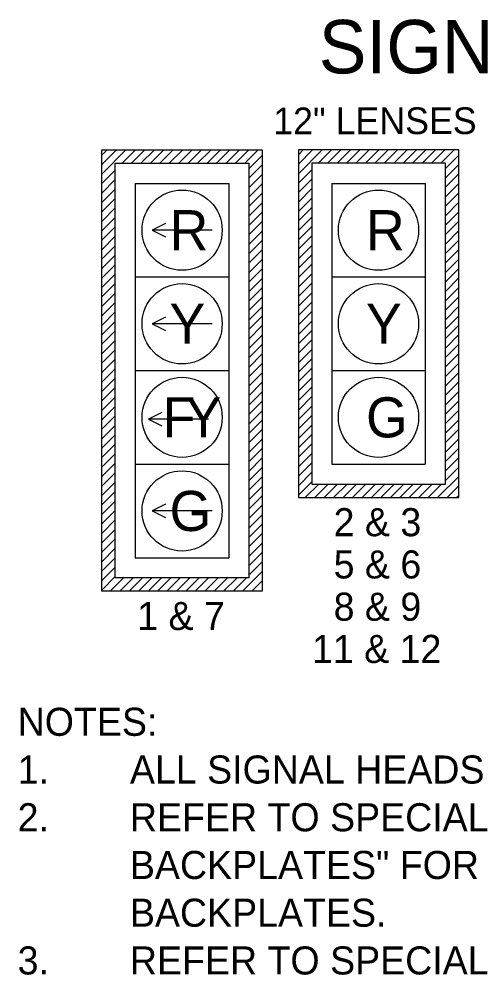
# Model space of a CAD drawing. Extents: x 418532 to 419834, y -565899 to -565283.
# Drawn here: x 419059.3 to 419129, y -565425.8 to -565282.9 of the extents above; entities that cross this region are included whole.
import ezdxf

# ---------------------------------------------------------------- set-up
doc = ezdxf.new("R2010")
doc.units = 0
for name, color, linetype in [('C-ANNO-TEXT', 7, 'Continuous'), ('Level 61', 7, 'Continuous'), ('T_Drafting', 7, 'Continuous')]:
    doc.layers.add(name, color=color, linetype=linetype)

msp = doc.modelspace()

# ---------------------------------------------------------------- linework, layer by layer
at = {"layer": 'T_Drafting'}
for p, q in [((419071.67, -565368.43), (419071.67, -565302.43)), ((419071.67, -565302.43), (419095.67, -565302.43)), ((419071.67, -565306.04), (419075.27, -565302.43)), ((419071.67, -565304.62), (419073.86, -565302.43)), ((419071.67, -565303.21), (419072.45, -565302.43)), ((419074.69, -565304.43), (419076.69, -565302.43)), ((419076.1, -565304.43), (419078.1, -565302.43)), ((419077.52, -565304.43), (419079.52, -565302.43)), ((419078.93, -565304.43), (419080.93, -565302.43)), ((419080.35, -565304.43), (419082.35, -565302.43)), ((419081.76, -565304.43), (419083.76, -565302.43)), ((419083.17, -565304.43), (419085.17, -565302.43)), ((419084.59, -565304.43), (419086.59, -565302.43)), ((419086, -565304.43), (419088, -565302.43)), ((419087.42, -565304.43), (419089.42, -565302.43)), ((419088.83, -565304.43), (419090.83, -565302.43)), ((419090.25, -565304.43), (419092.25, -565302.43)), ((419091.66, -565304.43), (419093.66, -565302.43)), ((419093.07, -565304.43), (419095.07, -565302.43)), ((419095.67, -565302.43), (419095.67, -565368.43)), ((419125.07, -565302.43), (419101.07, -565302.43)), ((419101.07, -565302.43), (419101.07, -565354.43)), ((419101.07, -565305.98), (419104.61, -565302.43)), ((419101.07, -565304.56), (419103.2, -565302.43)), ((419101.07, -565303.15), (419101.78, -565302.43)), ((419104.03, -565304.43), (419106.03, -565302.43)), ((419105.44, -565304.43), (419107.44, -565302.43)), ((419106.86, -565304.43), (419108.86, -565302.43)), ((419108.27, -565304.43), (419110.27, -565302.43)), ((419109.68, -565304.43), (419111.68, -565302.43)), ((419111.1, -565304.43), (419113.1, -565302.43)), ((419112.51, -565304.43), (419114.51, -565302.43)), ((419113.93, -565304.43), (419115.93, -565302.43)), ((419115.34, -565304.43), (419117.34, -565302.43)), ((419116.75, -565304.43), (419118.75, -565302.43)), ((419118.17, -565304.43), (419120.17, -565302.43)), ((419119.58, -565304.43), (419121.58, -565302.43)), ((419121, -565304.43), (419123, -565302.43)), ((419122.41, -565304.43), (419124.41, -565302.43)), ((419125.07, -565354.43), (419125.07, -565302.43)), ((419093.67, -565305.25), (419095.67, -565303.25)), ((419123.07, -565305.19), (419125.07, -565303.19)), ((419093.67, -565306.67), (419095.67, -565304.67)), ((419123.07, -565306.61), (419125.07, -565304.61)), ((419071.67, -565307.45), (419073.67, -565305.45)), ((419093.67, -565308.08), (419095.67, -565306.08)), ((419101.07, -565307.39), (419103.07, -565305.39)), ((419101.07, -565308.81), (419103.07, -565306.81)), ((419123.07, -565308.02), (419125.07, -565306.02)), ((419071.67, -565308.87), (419073.67, -565306.87)), ((419076.67, -565307.43), (419090.67, -565307.43)), ((419076.67, -565307.43), (419076.67, -565321.43)), ((419090.67, -565307.43), (419090.67, -565321.43)), ((419093.67, -565309.49), (419095.67, -565307.49)), ((419101.07, -565310.22), (419103.07, -565308.22)), ((419106.07, -565307.43), (419120.07, -565307.43)), ((419106.07, -565307.43), (419106.07, -565321.43)), ((419120.07, -565307.43), (419120.07, -565321.43)), ((419123.07, -565309.43), (419125.07, -565307.43)), ((419071.67, -565310.28), (419073.67, -565308.28)), ((419093.67, -565310.91), (419095.67, -565308.91)), ((419101.07, -565311.63), (419103.07, -565309.63)), ((419123.07, -565310.85), (419125.07, -565308.85)), ((419071.67, -565311.7), (419073.67, -565309.7)), ((419093.67, -565312.32), (419095.67, -565310.32)), ((419101.07, -565313.05), (419103.07, -565311.05)), ((419123.07, -565312.26), (419125.07, -565310.26)), ((419071.67, -565313.11), (419073.67, -565311.11)), ((419071.67, -565314.52), (419073.67, -565312.52)), ((419093.67, -565313.74), (419095.67, -565311.74)), ((419101.07, -565314.46), (419103.07, -565312.46)), ((419123.07, -565313.68), (419125.07, -565311.68)), ((419071.67, -565315.94), (419073.67, -565313.94)), ((419093.67, -565315.15), (419095.67, -565313.15)), ((419101.07, -565315.88), (419103.07, -565313.88)), ((419123.07, -565315.09), (419125.07, -565313.09)), ((419071.67, -565317.35), (419073.67, -565315.35)), ((419088.17, -565314.43), (419079.17, -565314.43)), ((419093.67, -565316.57), (419095.67, -565314.57)), ((419101.07, -565317.29), (419103.07, -565315.29)), ((419123.07, -565316.5), (419125.07, -565314.5)), ((419071.67, -565318.77), (419073.67, -565316.77)), ((419093.67, -565317.98), (419095.67, -565315.98)), ((419101.07, -565318.71), (419103.07, -565316.71)), ((419123.07, -565317.92), (419125.07, -565315.92)), ((419071.67, -565320.18), (419073.67, -565318.18)), ((419093.67, -565319.39), (419095.67, -565317.39)), ((419101.07, -565320.12), (419103.07, -565318.12)), ((419123.07, -565319.33), (419125.07, -565317.33)), ((419071.67, -565321.59), (419073.67, -565319.59)), ((419093.67, -565320.81), (419095.67, -565318.81)), ((419101.07, -565321.53), (419103.07, -565319.53)), ((419123.07, -565320.75), (419125.07, -565318.75)), ((419071.67, -565323.01), (419073.67, -565321.01)), ((419093.67, -565322.22), (419095.67, -565320.22)), ((419101.07, -565322.95), (419103.07, -565320.95)), ((419123.07, -565322.16), (419125.07, -565320.16)), ((419071.67, -565324.42), (419073.67, -565322.42)), ((419076.67, -565321.43), (419090.67, -565321.43)), ((419076.67, -565321.43), (419076.67, -565335.43)), ((419090.67, -565321.43), (419090.67, -565335.43)), ((419093.67, -565323.64), (419095.67, -565321.64)), ((419101.07, -565324.36), (419103.07, -565322.36)), ((419106.07, -565321.43), (419120.07, -565321.43)), ((419106.07, -565321.43), (419106.07, -565335.43)), ((419120.07, -565321.43), (419120.07, -565335.43)), ((419123.07, -565323.58), (419125.07, -565321.58)), ((419071.67, -565325.84), (419073.67, -565323.84)), ((419093.67, -565325.05), (419095.67, -565323.05)), ((419101.07, -565325.78), (419103.07, -565323.78)), ((419123.07, -565324.99), (419125.07, -565322.99)), ((419071.67, -565327.25), (419073.67, -565325.25)), ((419093.67, -565326.46), (419095.67, -565324.46)), ((419101.07, -565327.19), (419103.07, -565325.19)), ((419123.07, -565326.4), (419125.07, -565324.4)), ((419071.67, -565328.67), (419073.67, -565326.67)), ((419093.67, -565327.88), (419095.67, -565325.88)), ((419101.07, -565328.61), (419103.07, -565326.61)), ((419123.07, -565327.82), (419125.07, -565325.82)), ((419071.67, -565330.08), (419073.67, -565328.08)), ((419093.67, -565329.29), (419095.67, -565327.29)), ((419101.07, -565330.02), (419103.07, -565328.02)), ((419123.07, -565329.23), (419125.07, -565327.23)), ((419071.67, -565331.49), (419073.67, -565329.49)), ((419088.17, -565328.43), (419079.17, -565328.43)), ((419093.67, -565330.71), (419095.67, -565328.71)), ((419101.07, -565331.43), (419103.07, -565329.43)), ((419123.07, -565330.65), (419125.07, -565328.65)), ((419071.67, -565332.91), (419073.67, -565330.91)), ((419093.67, -565332.12), (419095.67, -565330.12)), ((419101.07, -565332.85), (419103.07, -565330.85)), ((419123.07, -565332.06), (419125.07, -565330.06)), ((419071.67, -565334.32), (419073.67, -565332.32)), ((419093.67, -565333.54), (419095.67, -565331.54)), ((419101.07, -565334.26), (419103.07, -565332.26)), ((419123.07, -565333.48), (419125.07, -565331.48)), ((419071.67, -565335.74), (419073.67, -565333.74)), ((419093.67, -565334.95), (419095.67, -565332.95)), ((419101.07, -565335.68), (419103.07, -565333.68)), ((419123.07, -565334.89), (419125.07, -565332.89)), ((419071.67, -565337.15), (419073.67, -565335.15)), ((419093.67, -565336.36), (419095.67, -565334.36)), ((419101.07, -565337.09), (419103.07, -565335.09)), ((419123.07, -565336.3), (419125.07, -565334.3)), ((419071.67, -565338.57), (419073.67, -565336.57)), ((419076.67, -565335.43), (419090.67, -565335.43)), ((419076.67, -565335.43), (419076.67, -565349.43)), ((419090.67, -565335.43), (419090.67, -565349.43)), ((419093.67, -565337.78), (419095.67, -565335.78)), ((419101.07, -565338.5), (419103.07, -565336.5)), ((419106.07, -565335.43), (419120.07, -565335.43)), ((419106.07, -565335.43), (419106.07, -565349.43)), ((419120.07, -565335.43), (419120.07, -565349.43)), ((419123.07, -565337.72), (419125.07, -565335.72)), ((419071.67, -565339.98), (419073.67, -565337.98)), ((419093.67, -565339.19), (419095.67, -565337.19)), ((419101.07, -565339.92), (419103.07, -565337.92)), ((419123.07, -565339.13), (419125.07, -565337.13)), ((419071.67, -565341.39), (419073.67, -565339.39)), ((419093.67, -565340.61), (419095.67, -565338.61)), ((419101.07, -565341.33), (419103.07, -565339.33)), ((419123.07, -565340.55), (419125.07, -565338.55)), ((419071.67, -565342.81), (419073.67, -565340.81)), ((419093.67, -565342.02), (419095.67, -565340.02)), ((419101.07, -565342.75), (419103.07, -565340.75)), ((419123.07, -565341.96), (419125.07, -565339.96)), ((419071.67, -565344.22), (419073.67, -565342.22)), ((419093.67, -565343.44), (419095.67, -565341.44)), ((419101.07, -565344.16), (419103.07, -565342.16)), ((419123.07, -565343.37), (419125.07, -565341.37)), ((419071.67, -565345.64), (419073.67, -565343.64)), ((419087.64, -565342.71), (419078.64, -565342.71)), ((419093.67, -565344.85), (419095.67, -565342.85)), ((419101.07, -565345.58), (419103.07, -565343.58)), ((419123.07, -565344.79), (419125.07, -565342.79)), ((419071.67, -565347.05), (419073.67, -565345.05)), ((419093.67, -565346.26), (419095.67, -565344.26)), ((419101.07, -565346.99), (419103.07, -565344.99)), ((419123.07, -565346.2), (419125.07, -565344.2)), ((419071.67, -565348.46), (419073.67, -565346.46)), ((419093.67, -565347.68), (419095.67, -565345.68)), ((419101.07, -565348.4), (419103.07, -565346.4)), ((419123.07, -565347.62), (419125.07, -565345.62)), ((419071.67, -565349.88), (419073.67, -565347.88)), ((419093.67, -565349.09), (419095.67, -565347.09)), ((419101.07, -565349.82), (419103.07, -565347.82)), ((419123.07, -565349.03), (419125.07, -565347.03)), ((419071.67, -565351.29), (419073.67, -565349.29)), ((419076.67, -565349.43), (419090.67, -565349.43)), ((419076.67, -565349.43), (419076.67, -565363.43)), ((419090.67, -565349.43), (419090.67, -565363.43)), ((419093.67, -565350.51), (419095.67, -565348.51)), ((419101.07, -565351.23), (419103.07, -565349.23)), ((419106.07, -565349.43), (419120.07, -565349.43)), ((419123.07, -565350.45), (419125.07, -565348.45)), ((419071.67, -565352.71), (419073.67, -565350.71)), ((419093.67, -565351.92), (419095.67, -565349.92)), ((419101.07, -565352.65), (419103.07, -565350.65)), ((419123.07, -565351.86), (419125.07, -565349.86)), ((419071.67, -565354.12), (419073.67, -565352.12)), ((419093.67, -565353.33), (419095.67, -565351.33)), ((419101.07, -565354.06), (419103.07, -565352.06)), ((419102.11, -565354.43), (419104.11, -565352.43)), ((419103.52, -565354.43), (419105.52, -565352.43)), ((419104.94, -565354.43), (419106.94, -565352.43)), ((419106.35, -565354.43), (419108.35, -565352.43)), ((419107.77, -565354.43), (419109.77, -565352.43)), ((419109.18, -565354.43), (419111.18, -565352.43)), ((419110.6, -565354.43), (419112.6, -565352.43)), ((419112.01, -565354.43), (419114.01, -565352.43)), ((419113.42, -565354.43), (419115.42, -565352.43)), ((419114.84, -565354.43), (419116.84, -565352.43)), ((419116.25, -565354.43), (419118.25, -565352.43)), ((419117.67, -565354.43), (419119.67, -565352.43)), ((419119.08, -565354.43), (419121.08, -565352.43)), ((419120.49, -565354.43), (419122.49, -565352.43)), ((419121.91, -565354.43), (419125.07, -565351.27)), ((419071.67, -565355.54), (419073.67, -565353.54)), ((419093.67, -565354.75), (419095.67, -565352.75)), ((419123.32, -565354.43), (419125.07, -565352.69)), ((419071.67, -565356.95), (419073.67, -565354.95)), ((419093.67, -565356.16), (419095.67, -565354.16)), ((419101.07, -565354.43), (419125.07, -565354.43)), ((419124.74, -565354.43), (419125.07, -565354.1)), ((419071.67, -565358.36), (419073.67, -565356.36)), ((419088.17, -565356.43), (419079.17, -565356.43)), ((419093.67, -565357.58), (419095.67, -565355.58)), ((419071.67, -565359.78), (419073.67, -565357.78)), ((419093.67, -565358.99), (419095.67, -565356.99)), ((419071.67, -565361.19), (419073.67, -565359.19)), ((419093.67, -565360.41), (419095.67, -565358.41)), ((419071.67, -565362.61), (419073.67, -565360.61)), ((419093.67, -565361.82), (419095.67, -565359.82)), ((419071.67, -565364.02), (419073.67, -565362.02)), ((419093.67, -565363.23), (419095.67, -565361.23)), ((419071.67, -565365.44), (419073.67, -565363.44)), ((419076.67, -565363.43), (419090.67, -565363.43)), ((419093.67, -565364.65), (419095.67, -565362.65)), ((419071.67, -565366.85), (419073.67, -565364.85)), ((419093.67, -565366.06), (419095.67, -565364.06)), ((419071.67, -565368.26), (419073.67, -565366.26)), ((419072.91, -565368.43), (419074.91, -565366.43)), ((419074.33, -565368.43), (419076.33, -565366.43)), ((419075.74, -565368.43), (419077.74, -565366.43)), ((419077.16, -565368.43), (419079.16, -565366.43)), ((419078.57, -565368.43), (419080.57, -565366.43)), ((419079.99, -565368.43), (419081.99, -565366.43)), ((419081.4, -565368.43), (419083.4, -565366.43)), ((419082.81, -565368.43), (419084.81, -565366.43)), ((419084.23, -565368.43), (419086.23, -565366.43)), ((419085.64, -565368.43), (419087.64, -565366.43)), ((419087.06, -565368.43), (419089.06, -565366.43)), ((419088.47, -565368.43), (419090.47, -565366.43)), ((419089.89, -565368.43), (419091.89, -565366.43)), ((419091.3, -565368.43), (419093.3, -565366.43)), ((419092.71, -565368.43), (419095.67, -565365.48)), ((419094.13, -565368.43), (419095.67, -565366.89)), ((419095.67, -565368.43), (419071.67, -565368.43)), ((419095.54, -565368.43), (419095.67, -565368.31))]:
    msp.add_line(p, q, dxfattribs=at)
for points in [[(419073.67, -565366.43), (419073.67, -565304.43), (419093.67, -565304.43), (419093.67, -565366.43)], [(419123.07, -565352.43), (419123.07, -565304.43), (419103.07, -565304.43), (419103.07, -565352.43)]]:
    msp.add_lwpolyline(points, close=True, dxfattribs=at)
for points in [[(419081.17, -565313.43), (419079.17, -565314.43), (419081.17, -565315.43)], [(419081.17, -565327.43), (419079.17, -565328.43), (419081.17, -565329.43)], [(419080.64, -565341.71), (419078.64, -565342.71), (419080.64, -565343.71)], [(419081.17, -565355.43), (419079.17, -565356.43), (419081.17, -565357.43)]]:
    msp.add_lwpolyline(points, dxfattribs=at)
for centre in [(419083.67, -565314.43), (419113.07, -565314.43), (419083.67, -565328.43), (419113.07, -565328.43), (419083.67, -565342.43), (419113.07, -565342.43), (419083.67, -565356.43)]:
    msp.add_circle(centre, 6, dxfattribs=at)

# ---------------------------------------------------------------- texts
at = {"layer": 'C-ANNO-TEXT'}
for s, p in [('2 & 3', (419106.35, -565360.21)), ('5 & 6', (419106.35, -565366.53)), ('8 & 9', (419106.35, -565372.85)), ('1 & 7', (419076.95, -565374.24)), ('11 & 12', (419103.11, -565379.17)), ('NOTES:', (419059.06, -565390.07)), ('1.', (419059.06, -565397.21)), ('ALL SIGNAL HEADS SHALL HAVE BACKPLATES.', (419075.86, -565397.21)), ('2.', (419059.06, -565404.35)), ('REFER TO SPECIAL PROVISION "RETROREFLECTIVE', (419075.86, -565404.35)), ('BACKPLATES" FOR DETAILS ON REQUIREMENTS FOR ', (419075.86, -565411.49)), ('BACKPLATES.', (419075.86, -565418.63)), ('3.', (419059.06, -565425.77)), ('REFER TO SPECIAL PROVISIONS FOR DETAILS ON', (419075.86, -565425.77))]:
    msp.add_text(s, height=4.2, rotation=360, dxfattribs=at).set_placement(p)
at = {"layer": 'Level 61'}
msp.add_text('SIGNAL FACES', height=8, dxfattribs=at).set_placement((419104.12, -565290.98))
msp.add_text('12" LENSES', height=4, rotation=0.072, dxfattribs=at).set_placement((419097.31, -565300.09))
at = {"layer": 'T_Drafting'}
for s, p in [('R', (419081.8, -565317.43)), ('R', (419111.2, -565317.43)), ('Y', (419081.78, -565331.43)), ('Y', (419111.18, -565331.43)), ('F', (419080.76, -565345.43)), ('Y', (419084.19, -565345.43)), ('G', (419111.2, -565345.43)), ('G', (419081.8, -565359.43))]:
    msp.add_text(s, height=6, dxfattribs=at).set_placement(p)

doc.saveas('drawing.dxf')
